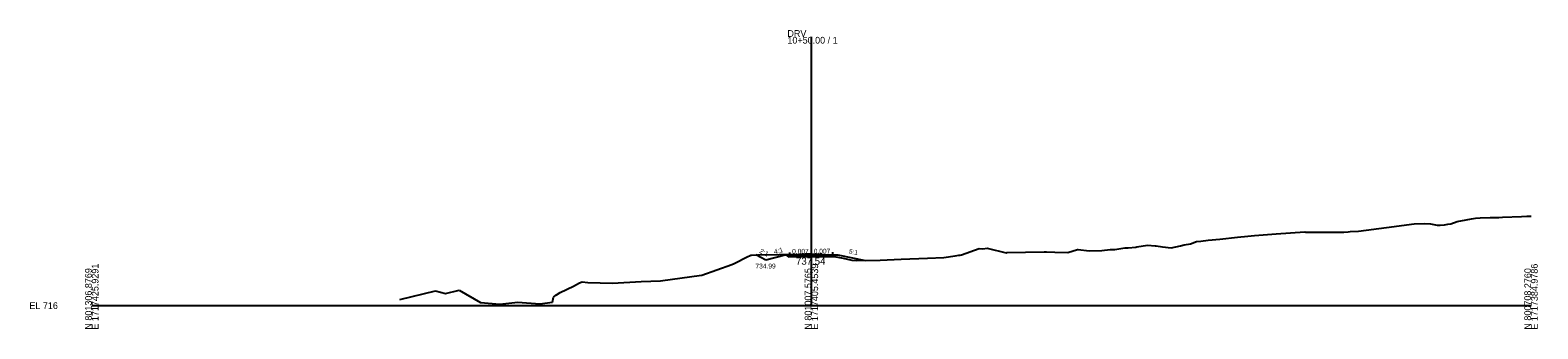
# Model space of a CAD drawing. Extents: x -26 to 603, y -10 to 3134.
# Drawn here: x -26 to 603, y 990 to 1115 of the extents above; entities that cross this region are included whole.
import ezdxf

# ---------------------------------------------------------------- set-up
doc = ezdxf.new("R2010")
doc.units = 0
for name, color, linetype in [('Exist Cross Section Cell', 7, 'Continuous'), ('Exist XS Center Line Elevation Label', 7, 'Continuous'), ('Exist XS Ground Line', 7, 'Continuous'), ('Prop XS Ditch Slope Text', 7, 'Continuous'), ('Prop XS Ditch Standard Text', 7, 'Continuous'), ('Prop XS Dump Level', 7, 'Continuous'), ('Prop XS EOT Tick Mark', 7, 'Continuous'), ('Prop XS Finish Grade', 7, 'Continuous'), ('Prop XS Finish Grade Earthwork', 7, 'Continuous'), ('Prop XS Finish Grade Pavement', 7, 'Continuous'), ('Prop XS Pvmt Edge Slope', 7, 'Continuous'), ('Prop XS SE Text', 7, 'Continuous'), ('Prop XS Side Slope Text', 7, 'Continuous'), ('Prop XS Subgrade Earthwork', 7, 'Continuous')]:
    doc.layers.add(name, color=color, linetype=linetype)

msp = doc.modelspace()

# ---------------------------------------------------------------- linework, layer by layer
at = {"layer": 'Exist Cross Section Cell'}
for p, q in [((300, 1000), (300, 1112.07)), ((0, 1000), (300, 1000)), ((300, 1000), (600, 1000))]:
    msp.add_line(p, q, dxfattribs=at)
at = {"layer": 'Exist XS Ground Line'}
for p, q in [((588.06, 1036.83), (595.98, 1037.22)), ((595.98, 1037.22), (598.19, 1037.36)), ((598.19, 1037.36), (600, 1037.34)), ((523.78, 1030.77), (524.58, 1030.88)), ((524.58, 1030.88), (528.08, 1031.05)), ((528.08, 1031.05), (539.72, 1032.52)), ((539.72, 1032.52), (551.31, 1034.06)), ((551.31, 1034.06), (555.53, 1034.3)), ((555.53, 1034.3), (558.07, 1034.05)), ((558.07, 1034.05), (560.83, 1033.6)), ((560.83, 1033.6), (562.05, 1033.58)), ((562.05, 1033.58), (563.94, 1033.7)), ((563.94, 1033.7), (565.35, 1033.91)), ((565.35, 1033.91), (566.57, 1034.16)), ((566.57, 1034.16), (569.17, 1035.07)), ((569.17, 1035.07), (572.93, 1035.75)), ((572.93, 1035.75), (575.18, 1036.12)), ((575.18, 1036.12), (576.85, 1036.5)), ((576.85, 1036.5), (578.79, 1036.64)), ((578.79, 1036.64), (583.01, 1036.72)), ((583.01, 1036.72), (586.54, 1036.7)), ((586.54, 1036.7), (588.06, 1036.83)), ((435.71, 1024.46), (440.12, 1025.18)), ((440.12, 1025.18), (443.32, 1024.97)), ((443.32, 1024.97), (443.69, 1024.94)), ((443.69, 1024.94), (446.38, 1024.52)), ((446.38, 1024.52), (450.03, 1024.15)), ((450.03, 1024.15), (453.83, 1024.9)), ((453.83, 1024.9), (455.34, 1025.41)), ((455.34, 1025.41), (458.04, 1025.77)), ((458.04, 1025.77), (460.54, 1026.79)), ((460.54, 1026.79), (462.31, 1026.94)), ((462.31, 1026.94), (465.4, 1027.31)), ((465.4, 1027.31), (470.31, 1027.73)), ((470.31, 1027.73), (477.65, 1028.53)), ((477.65, 1028.53), (481.89, 1029.02)), ((481.89, 1029.02), (484.7, 1029.29)), ((484.7, 1029.29), (493.78, 1029.88)), ((493.78, 1029.88), (505.72, 1030.71)), ((505.72, 1030.71), (506.12, 1030.69)), ((506.12, 1030.69), (506.42, 1030.69)), ((506.42, 1030.69), (522.02, 1030.58)), ((522.02, 1030.58), (523.78, 1030.77)), ((267.79, 1017.63), (273.48, 1020.42)), ((273.48, 1020.42), (274.24, 1020.69)), ((274.24, 1020.69), (274.78, 1021.01)), ((274.78, 1021.01), (275.07, 1021.03)), ((275.07, 1021.03), (277.48, 1021.14)), ((277.48, 1021.14), (295.45, 1021.51)), ((295.45, 1021.51), (297.46, 1021.57)), ((297.46, 1021.57), (298.65, 1021.55)), ((298.65, 1021.55), (300, 1021.54)), ((300, 1021.54), (304.2, 1021.51)), ((304.2, 1021.51), (313.22, 1019.75)), ((313.22, 1019.75), (316.8, 1018.97)), ((316.8, 1018.97), (318.83, 1018.78)), ((318.83, 1018.78), (328.73, 1018.9)), ((328.73, 1018.9), (337.37, 1019.31)), ((337.37, 1019.31), (348.46, 1019.75)), ((348.46, 1019.75), (355.15, 1020)), ((355.15, 1020), (359.88, 1020.81)), ((359.88, 1020.81), (361.45, 1021)), ((361.45, 1021), (362.06, 1021.1)), ((362.06, 1021.1), (362.6, 1021.12)), ((362.6, 1021.12), (369.87, 1023.88)), ((369.87, 1023.88), (371.48, 1023.73)), ((371.48, 1023.73), (373.31, 1023.96)), ((373.31, 1023.96), (381.18, 1022.07)), ((381.18, 1022.07), (381.49, 1022.08)), ((381.49, 1022.08), (397.09, 1022.47)), ((397.09, 1022.47), (397.96, 1022.49)), ((397.96, 1022.49), (401.47, 1022.35)), ((401.47, 1022.35), (406.85, 1022.21)), ((406.85, 1022.21), (410.86, 1023.38)), ((410.86, 1023.38), (411, 1023.44)), ((411, 1023.44), (411.27, 1023.39)), ((411.27, 1023.39), (415.76, 1022.8)), ((415.76, 1022.8), (421.05, 1022.98)), ((421.05, 1022.98), (424.55, 1023.39)), ((424.55, 1023.39), (426.53, 1023.4)), ((426.53, 1023.4), (430.66, 1024.11)), ((430.66, 1024.11), (431.99, 1024.12)), ((431.99, 1024.12), (435.3, 1024.36)), ((435.3, 1024.36), (435.71, 1024.46)), ((237.14, 1010.31), (254.19, 1012.67)), ((254.19, 1012.67), (254.2, 1012.67)), ((254.2, 1012.67), (254.27, 1012.69)), ((254.2, 1012.67), (254.2, 1012.67)), ((254.27, 1012.69), (266.79, 1017.18)), ((266.79, 1017.18), (267.79, 1017.63)), ((128.37, 1002.5), (143.31, 1006.21)), ((143.31, 1006.21), (147.52, 1004.99)), ((147.52, 1004.99), (153.16, 1006.49)), ((153.16, 1006.49), (161.99, 1001.25)), ((195.27, 1005.43), (200.88, 1008.17)), ((200.88, 1008.17), (203.27, 1009.45)), ((203.27, 1009.45), (204.47, 1009.87)), ((204.47, 1009.87), (206.85, 1009.7)), ((206.85, 1009.7), (217.09, 1009.35)), ((217.09, 1009.35), (229.02, 1010.05)), ((229.02, 1010.05), (237.14, 1010.31)), ((161.99, 1001.25), (170.07, 1000.61)), ((170.07, 1000.61), (177.62, 1001.42)), ((177.62, 1001.42), (186.73, 1000.73)), ((186.73, 1000.73), (192.05, 1001.48)), ((192.05, 1001.48), (192.51, 1003.56)), ((192.51, 1003.56), (193.4, 1004.34)), ((193.4, 1004.34), (193.76, 1004.55)), ((193.76, 1004.55), (195.27, 1005.43))]:
    msp.add_line(p, q, dxfattribs=at)
at = {"layer": 'Prop XS Dump Level'}
for p, q in [((291, 1021.13), (300, 1021.19)), ((300, 1021.19), (309, 1021.25))]:
    msp.add_line(p, q, dxfattribs=at)
at = {"layer": 'Prop XS EOT Tick Mark'}
for p, q in [((291, 1021.13), (291, 1022.13)), ((309, 1021.25), (309, 1022.25))]:
    msp.add_line(p, q, dxfattribs=at)
at = {"layer": 'Prop XS Finish Grade'}
for p, q in [((291, 1021.13), (289.66, 1021.04)), ((309, 1021.25), (310.34, 1021.18))]:
    msp.add_line(p, q, dxfattribs=at)
at = {"layer": 'Prop XS Finish Grade Earthwork'}
for p, q in [((281, 1018.99), (276.77, 1021.11)), ((289, 1020.99), (281, 1018.99)), ((289.66, 1021.04), (289, 1020.99)), ((310.34, 1021.18), (311, 1021.14)), ((311, 1021.14), (322.57, 1018.83))]:
    msp.add_line(p, q, dxfattribs=at)
at = {"layer": 'Prop XS Finish Grade Pavement'}
for p, q in [((291, 1021.13), (300, 1021.19)), ((300, 1021.19), (309, 1021.25))]:
    msp.add_line(p, q, dxfattribs=at)
at = {"layer": 'Prop XS Pvmt Edge Slope'}
for p, q in [((291, 1021.13), (290.29, 1020.41)), ((309, 1021.25), (309.7, 1020.54))]:
    msp.add_line(p, q, dxfattribs=at)
at = {"layer": 'Prop XS Subgrade Earthwork'}
for p, q in [((290.29, 1020.41), (289.66, 1021.04)), ((290.29, 1020.41), (300, 1020.48)), ((300, 1020.48), (309.7, 1020.54)), ((309.7, 1020.54), (310.34, 1021.18))]:
    msp.add_line(p, q, dxfattribs=at)

# ---------------------------------------------------------------- texts
at = {"layer": 'Exist Cross Section Cell'}
for s, p in [('DRV', (290, 1112.07)), ('10+50.00 / 1', (290, 1109.27)), ('EL 716', (-26, 998.6))]:
    msp.add_text(s, height=2.8, dxfattribs=at).set_placement(p)
for s, p in [('N 801306.8769', (0, 990)), ('E 1717425.9291', (2.8, 990)), ('N 801007.5765', (300, 990)), ('E 1717405.4539', (302.8, 990)), ('N 800708.2760', (600, 990)), ('E 1717384.9786', (602.8, 990))]:
    msp.add_text(s, height=2.8, rotation=90, dxfattribs=at).set_placement(p)
at = {"layer": 'Exist XS Center Line Elevation Label'}
msp.add_text('737.54', height=3, dxfattribs=at).set_placement((293.57, 1017.04))
at = {"layer": 'Prop XS Ditch Slope Text'}
msp.add_text('4:1', height=2, rotation=14.03624, dxfattribs=at).set_placement((284.64, 1021.45))
at = {"layer": 'Prop XS Ditch Standard Text'}
msp.add_text('734.99', height=2, dxfattribs=at).set_placement((276.67, 1015.49))
at = {"layer": 'Prop XS Dump Level'}
for p in [(289, 1020.95), (311, 1021.1)]:
    msp.add_text('Case1', height=0.04, dxfattribs=at).set_placement(p)
at = {"layer": 'Prop XS SE Text'}
for p in [(291.97, 1021.63), (300.97, 1021.69)]:
    msp.add_text('0.007', height=2, rotation=0.38197, dxfattribs=at).set_placement(p)
at = {"layer": 'Prop XS Side Slope Text'}
for s, rotation, p in [('2:1', 333.43495, (278.11, 1022.12)), ('5:1', 348.69007, (315.49, 1021.77))]:
    msp.add_text(s, height=2, rotation=rotation, dxfattribs=at).set_placement(p)

doc.saveas('drawing.dxf')
